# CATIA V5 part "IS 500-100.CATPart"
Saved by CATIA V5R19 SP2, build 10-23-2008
Part number: IS 500-100
Bounding box of the stored display mesh (mm): x -22.494 to 22.494, y -22.494 to 22.494, z 0 to 285
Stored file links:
  C:\Users\Bora\Desktop\3D Katı model\IS serisi\IS 500\IS 500-100.CATPart
  C:\Program Files\Dassault Systemes\B19\intel_a\reffiles\standard\MetricThinPitch.txt
  C:\Program Files\Dassault Systemes\B19\intel_a\reffiles\standard\MetricThickPitch.txt
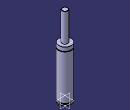
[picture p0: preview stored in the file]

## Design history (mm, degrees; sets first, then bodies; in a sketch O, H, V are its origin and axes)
Body1 (main body)
  Sketch1 on yz-plane, origin (0, 0, 0), H (0, 1, 0), V (0, 0, 1)
    point P3 (10, 284)
    point P5 (10, 284)
    point P7 (22.5, 169.5)
    point P8 (22.5, 167.5)
    point P12 (22.5, 167.5)
    point P13 (22.5, 169.5)
    line L1 (22.5, 0) -> (22.5, 4)
    line L2 (10, 284) -> (10, 183)
    arc A1 centre (9, 284) radius 1 from (10, 284) to (9, 285) ccw
    arc A2 centre (22.5, 168.5) radius 1 from (22.5, 169.5) to (22.5, 167.5) ccw
    line L3 (20, 7.5) -> (20, 4)
    line L4 (22.5, 7.5) -> (22.5, 167.5)
    line L5 (22.5, 169.5) -> (22.5, 183)
    line L6 (9, 285) -> (0, 285)
    point P15 (0, 285)
    line L7 (10, 183) -> (22.5, 183)
    line L8 (0, 0) -> (22.5, 0)
    line L9 (20, 4) -> (22.5, 4)
    line L10 (20, 7.5) -> (22.5, 7.5)
    coincidence: P15 V, P3 P5, P7 P13, P8 P12
    tangency: L6 A1
    horizontal: L7 H, L8 H, L9 H, L10 H
  Shaft1: profile Sketch1, axis Sketch1.V, angle 360
  Sketch2 on face of Shaft1 from Sketch1.L8, origin (0, 0, 0), H (1, 0, 0), V (0, -1, 0)
    point P1 (10, 0)
    distance P1 V = 10
  Hole1: placed by Sketch2, at (10, 0, 0) direction (0, 0, 1), diameter 6.647, depth 13, threaded "M8", thread diameter 8, thread depth 13, pitch 1.25
  Sketch3 on face of Shaft1 from Sketch1.L8, origin (0, 0, 0), H (1, 0, 0), V (0, -1, 0)
    point P1 (-10, 0)
    distance P1 V = 10
  Hole2: placed by Sketch3, at (-10, 0, 0) direction (0, 0, 1), diameter 6.647, depth 13, threaded "M8", thread diameter 8, thread depth 13, pitch 1.25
